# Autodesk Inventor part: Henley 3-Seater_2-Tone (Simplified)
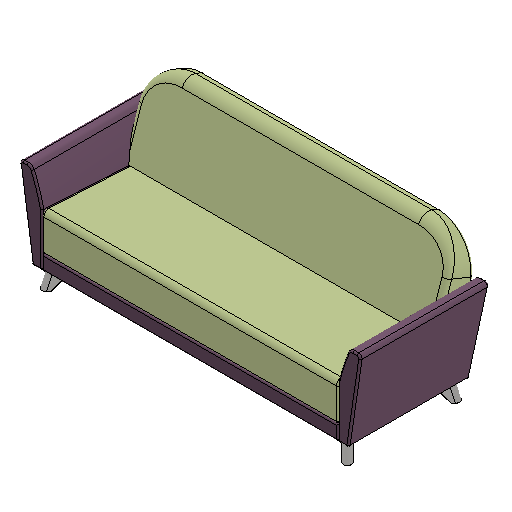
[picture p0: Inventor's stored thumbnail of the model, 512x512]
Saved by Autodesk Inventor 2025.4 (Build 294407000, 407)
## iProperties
Created: 2026-05
Part Number: Henley 3-Seater_2-Tone (Simplified)
Material: Generic
Description: 3-SEATER
Document SubType Name: Modeling
Designer: Brian.Thangei
Density: 1 g/cm^3
Appearance: Default
Project: HENLEY
Sending System: SolidWorks 2026
Preprocessor: SwSTEP 2.0
Title: Henley 3-Seater.STEP
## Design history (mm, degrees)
feature "NONE"
feature "NONE:1"
feature "NONE:2"
feature "NONE:3"
feature "NONE:4"
feature "NONE:5"
feature "NONE:6"
feature "NONE:7"
feature "NONE:8"
workplane "Work Plane1"
workplane "Work Plane2"
workplane "Work Plane3"
workplane "Work Plane4"
workplane "Work Plane5"
workplane "Work Plane6"
node "BASE"
node "ARM"
node "SEAT"
node "FOOT"
node "FOOT2"
node "BACK"
node "FOOT3"
node "ARM2"
node "FOOT4"
